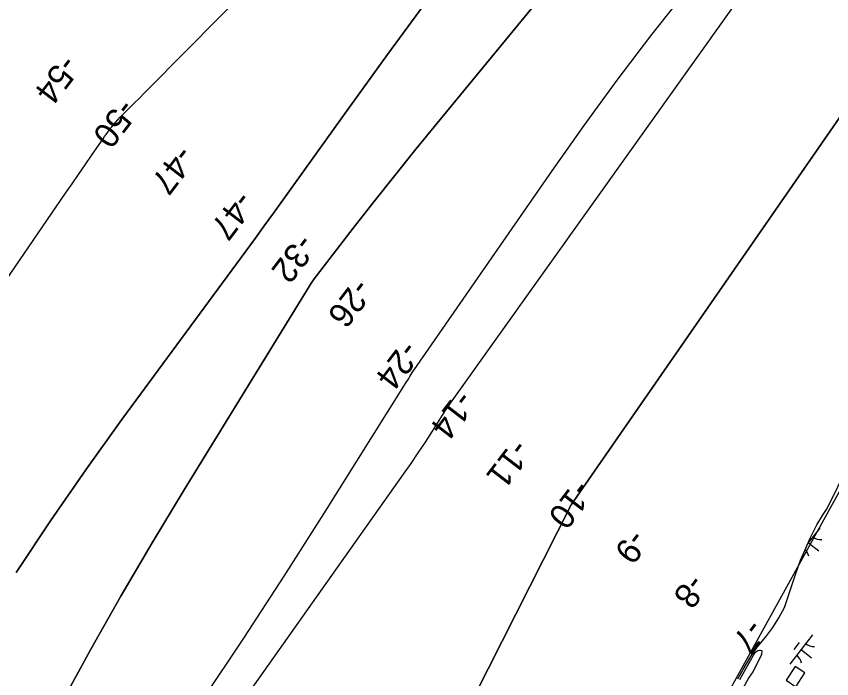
# Model space of a CAD drawing. Extents: x 3888273 to 3909528, y 158682 to 181032.
# Drawn here: x 3902388 to 3903492, y 171905 to 172801 of the extents above; entities that cross this region are included whole.
import ezdxf

# ---------------------------------------------------------------- set-up
doc = ezdxf.new("R2010")
doc.units = 0
for name, color, linetype in [('V-CHAN-DOCK', 7, 'Continuous'), ('V-RIVR-JETY', 7, 'Continuous'), ('V-RIVR-RANG', 7, 'Continuous'), ('V-RRAP-FSHR', 7, 'Continuous'), ('V-TOPO-DPTH', 7, 'Continuous'), ('V-TOPO-MAJR', 7, 'Continuous'), ('V-TOPO-MINR', 7, 'Continuous'), ('V-WETL-SWMP', 7, 'Continuous')]:
    doc.layers.add(name, color=color, linetype=linetype)

msp = doc.modelspace()

# ---------------------------------------------------------------- linework, layer by layer
at = {"layer": 'V-CHAN-DOCK'}
msp.add_lwpolyline([(3903442.7, 171921.3), (3903430.2, 171902.5), (3903443.4, 171893.7), (3903455.9, 171912.5)], close=True, dxfattribs=at)
at = {"layer": 'V-RIVR-JETY'}
msp.add_lwpolyline([(3903372.1, 171891.9), (3903379.5, 171904.7), (3903385.8, 171913.9), (3903396.7, 171935.9), (3903397.5, 171937.5), (3903397.8, 171941.9), (3903397.4, 171942.3), (3903395.8, 171942.7), (3903394.3, 171942.6), (3903391.9, 171942.2), (3903387.5, 171939.4), (3903367.2, 171903)], dxfattribs=at)
at = {"layer": 'V-RRAP-FSHR'}
msp.add_lwpolyline([(3902466.4, 170877.4), (3902596.5, 171071.9), (3902658.3, 171152.9), (3902704.7, 171211.9), (3903018.7, 171557.6), (3903166.9, 171672.4), (3903285.6, 171793.8), (3903327.1, 171840.6), (3903602.2, 172338.5), (3903762.1, 172628.9), (3903775.9, 172650.6), (3904124.4, 172985.1), (3904135.8, 173004.7), (3904140.8, 173195.6), (3904143.9, 173228.6), (3904155.6, 173256.3), (3904478.6, 173695.6), (3904503.4, 173735), (3904568.4, 173920.2), (3904627.6, 174008.5), (3904693.9, 174118.3), (3904723.9, 174185.4), (3904740.7, 174228.4), (3904769.8, 174251)], dxfattribs=at)
at = {"layer": 'V-TOPO-DPTH'}
for points in [[(3904753.3, 174263.4), (3904639.9, 174067), (3904618.4, 174039.2), (3904581.1, 173979.8), (3904522.2, 173904.5), (3904462.8, 173829.5), (3904403.2, 173754.8), (3904119.6, 173401.3), (3904117.5, 173398.6), (3904115.3, 173396), (3904113.1, 173393.3), (3904111, 173390.6), (3904094.7, 173370.8), (3904084.4, 173358.3), (3904074, 173345.9), (3904063.4, 173333.5), (3904052.8, 173321.2), (3903592.8, 172794.1), (3903139.4, 172139.9), (3902765.2, 171401.2)], [(3903281.7, 173050), (3902957.8, 172656.5), (3902929, 172621.2), (3902900.5, 172585.8), (3902872.3, 172550.1), (3902844.3, 172514.2), (3902790.2, 172444.2), (3902789.5, 172443.1), (3902787.2, 172440), (3902785.8, 172437.8), (3902784.4, 172435.6), (3902615.2, 172160.4), (3902572, 172088.7), (3902529.6, 172016.5), (3902488.5, 171943.6), (3902448.2, 171870.2)], [(3902448.2, 171870.2), (3902488.5, 171943.6), (3902529.6, 172016.5), (3902572, 172088.7), (3902615.2, 172160.4), (3902784.4, 172435.6), (3902785.8, 172437.8), (3902787.2, 172440), (3902789.5, 172443.1), (3902790.2, 172444.2), (3902844.3, 172514.2), (3902872.3, 172550.1), (3902900.5, 172585.8), (3902929, 172621.2), (3902957.8, 172656.5), (3903281.7, 173050)], [(3902950.7, 172831.7), (3902890.6, 172749.3), (3902831, 172666.8), (3902736.4, 172534.8), (3902723.9, 172517.6), (3902711.5, 172500.3), (3902698.9, 172483.2), (3902686.4, 172466), (3902531, 172255.2), (3902482.1, 172187.1), (3902434.3, 172118.3), (3902388.1, 172048.4)], [(3902388.1, 172048.4), (3902434.3, 172118.3), (3902482.1, 172187.1), (3902531, 172255.2), (3902686.4, 172466), (3902698.9, 172483.2), (3902711.5, 172500.3), (3902723.9, 172517.6), (3902736.4, 172534.8), (3902831, 172666.8), (3902890.6, 172749.3), (3902950.7, 172831.7)], [(3902640.6, 171876.4), (3902696.2, 171959.6), (3902750.8, 172043.5), (3902804.6, 172127.9), (3902915.2, 172304.1), (3902916.6, 172306.5), (3902918.1, 172308.8), (3902919.4, 172311.1), (3902920.8, 172313.5), (3902922.2, 172315.9), (3902923.6, 172318.2), (3902925.1, 172320.5), (3902926.6, 172322.7), (3903113.5, 172591.9), (3903157.1, 172653.5), (3903201.6, 172714.5), (3903247.3, 172774.5), (3903293.9, 172834)], [(3902640.6, 171876.4), (3902696.2, 171959.6), (3902750.8, 172043.5), (3902804.6, 172127.9), (3902915.2, 172304.1), (3902916.6, 172306.5), (3902918.1, 172308.8), (3902919.4, 172311.1), (3902920.8, 172313.5), (3902922.2, 172315.9), (3902923.6, 172318.2), (3902925.1, 172320.5), (3902926.6, 172322.7), (3903113.5, 172591.9), (3903157.1, 172653.5), (3903201.6, 172714.5), (3903247.3, 172774.5), (3903293.9, 172834)]]:
    msp.add_lwpolyline(points, dxfattribs=at)
at = {"layer": 'V-TOPO-MAJR'}
msp.add_lwpolyline([(3902182.4, 172164.1), (3902454.9, 172561.6), (3902463.7, 172574.3), (3902472.5, 172587.1), (3902481.2, 172599.9), (3902490, 172612.7), (3902503.3, 172632), (3902505.5, 172635.1), (3902507.6, 172638.2), (3902509.8, 172641.2), (3902512, 172644.2), (3902515.3, 172648.8), (3902515.8, 172649.5), (3902517, 172651), (3902517.6, 172651.7), (3902522.5, 172657.4), (3902525.6, 172661), (3902528.7, 172664.5), (3902532, 172667.9), (3902535.3, 172671.2), (3902541.7, 172677.5), (3902548.2, 172684), (3902554.7, 172690.5), (3902561.2, 172697), (3902567.7, 172703.5), (3902855.7, 172995)], dxfattribs=at)
at = {"layer": 'V-TOPO-MINR'}
for points in [[(3902765.2, 171401.2), (3903139.4, 172139.9), (3903592.8, 172794.1), (3904052.8, 173321.2), (3904063.4, 173333.5), (3904074, 173345.9), (3904084.4, 173358.3), (3904094.7, 173370.8), (3904111, 173390.6), (3904113.1, 173393.3), (3904115.3, 173396), (3904117.5, 173398.6), (3904119.6, 173401.3), (3904403.2, 173754.8), (3904462.8, 173829.5), (3904522.2, 173904.5), (3904581.1, 173979.8), (3904618.4, 174039.2), (3904639.9, 174067), (3904753.3, 174263.4)], [(3902448.2, 171870.2), (3902488.5, 171943.6), (3902529.6, 172016.5), (3902572, 172088.7), (3902615.2, 172160.4), (3902784.4, 172435.6), (3902785.8, 172437.8), (3902787.2, 172440), (3902789.5, 172443.1), (3902790.2, 172444.2), (3902844.3, 172514.2), (3902872.3, 172550.1), (3902900.5, 172585.8), (3902929, 172621.2), (3902957.8, 172656.5), (3903281.7, 173050)], [(3902503.4, 171603.5), (3902912.5, 172181.4), (3902922.5, 172195.8), (3902932.3, 172210.2), (3902941.9, 172224.9), (3902951.4, 172239.6), (3902969.6, 172268.4), (3902970, 172269.1), (3902971.5, 172271.4), (3903424.7, 172906.5)], [(3902388.1, 172048.4), (3902434.3, 172118.3), (3902482.1, 172187.1), (3902531, 172255.2), (3902686.4, 172466), (3902698.9, 172483.2), (3902711.5, 172500.3), (3902723.9, 172517.6), (3902736.4, 172534.8), (3902831, 172666.8), (3902890.6, 172749.3), (3902950.7, 172831.7)], [(3902640.6, 171876.4), (3902696.2, 171959.6), (3902750.8, 172043.5), (3902804.6, 172127.9), (3902915.2, 172304.1), (3902916.6, 172306.5), (3902918.1, 172308.8), (3902919.4, 172311.1), (3902920.8, 172313.5), (3902922.2, 172315.9), (3902923.6, 172318.2), (3902925.1, 172320.5), (3902926.6, 172322.7), (3903113.5, 172591.9), (3903157.1, 172653.5), (3903201.6, 172714.5), (3903247.3, 172774.5), (3903293.9, 172834)]]:
    msp.add_lwpolyline(points, dxfattribs=at)
at = {"layer": 'V-WETL-SWMP'}
for p, q in [((3903485.9, 172135), (3903514.2, 172192.9)), ((3903472, 172112.9), (3903479.7, 172125.5)), ((3903479.7, 172125.5), (3903485.9, 172135)), ((3903475.9, 172108.4), (3903459.9, 172087.9)), ((3903462.8, 172094.8), (3903472, 172112.9)), ((3903455.9, 172078.3), (3903462.8, 172094.8)), ((3903460.5, 172088.7), (3903474.7, 172077.6)), ((3903449.8, 172064.9), (3903455.9, 172078.3)), ((3903442.9, 172045.6), (3903449.8, 172064.9)), ((3903437.6, 172029.5), (3903442.9, 172045.6)), ((3903433.1, 172015.8), (3903437.6, 172029.5)), ((3903428.1, 172001.2), (3903433.1, 172015.8)), ((3903420.4, 171987), (3903428.1, 172001.2)), ((3903412.3, 171974), (3903420.4, 171987)), ((3903403.1, 171961.4), (3903412.3, 171974)), ((3903391.1, 171947.2), (3903403.1, 171961.4)), ((3903465.9, 171963.8), (3903435.2, 171924.4)), ((3903448.1, 171953.6), (3903440.8, 171944.1)), ((3903382.6, 171934.9), (3903391.1, 171947.2)), ((3903450.6, 171944.1), (3903464.8, 171933.1)), ((3903372.2, 171917.2), (3903382.6, 171934.9)), ((3903364.9, 171904.6), (3903372.2, 171917.2))]:
    msp.add_line(p, q, dxfattribs=at)
for centre, start, end in [((3903477.7, 172110.4), 231.343, 272.8866), ((3903443.7, 172066.8), 11.343, 44.7018), ((3903467.7, 171965.8), 231.343, 272.8866), ((3903433.8, 171922.2), 11.343, 52.8866)]:
    msp.add_arc(centre, 17.6, start, end, dxfattribs=at)

# ---------------------------------------------------------------- texts
at = {"layer": 'V-RIVR-RANG'}
for s, rotation, p in [('-54', 232.6536, (3902450.7, 172750.9)), ('-50', 232.6536, (3902529.2, 172691.6)), ('-47', 232.6536, (3902607.5, 172628.6)), ('-47', 232.6536, (3902688, 172567)), ('-32', 232.6536, (3902771.1, 172508.8)), ('-26', 232.6536, (3902847.4, 172448.5)), ('-24', 232.5083, (3902912.4, 172364.3)), ('-14', 232.5083, (3902986.7, 172296.9)), ('-11', 232.5083, (3903062.1, 172230.8)), ('-10', 232.5083, (3903146, 172176)), ('-9', 232.5083, (3903220.6, 172108.9)), ('-8', 232.5083, (3903300.3, 172048.5)), ('-7', 232.5083, (3903379.6, 171987.7))]:
    msp.add_text(s, height=33.5, rotation=rotation, dxfattribs=at).set_placement(p)

doc.saveas('drawing.dxf')
